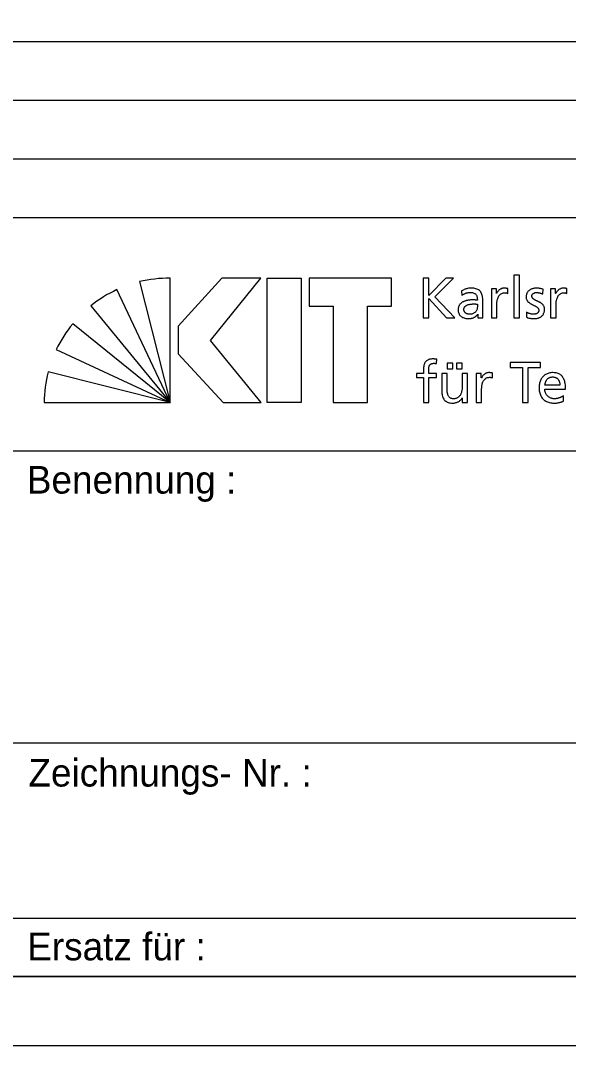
# Model space of a CAD drawing. Extents: x 0 to 8.41, y 0 to 5.94.
# Drawn here: x 7.527 to 7.923, y 0 to 0.742 of the extents above; entities that cross this region are included whole.
import ezdxf

# ---------------------------------------------------------------- set-up
doc = ezdxf.new("R2010")
doc.units = 0
doc.layers.add('90_Plankopf', color=7, linetype='Continuous')

msp = doc.modelspace()

# ---------------------------------------------------------------- linework, layer by layer
at = {"layer": '90_Plankopf'}
for p, q in [((6.5812, 0.7274), (8.36, 0.7274)), ((6.5812, 0.6849), (8.36, 0.6849)), ((6.5812, 0.6424), (8.36, 0.6424)), ((6.5812, 0.5999), (8.36, 0.5999)), ((6.5812, 0.5999), (8.36, 0.5999)), ((7.61275, 0.55333), (7.63481, 0.46586)), ((7.63481, 0.46586), (7.63481, 0.55584)), ((7.8181, 0.55586), (7.8181, 0.52706)), ((7.63481, 0.46586), (7.59633, 0.54752)), ((7.84579, 0.54662), (7.846, 0.54332)), ((7.87926, 0.54484), (7.87926, 0.54831)), ((7.90457, 0.54439), (7.9049, 0.54778)), ((7.92211, 0.54484), (7.92211, 0.54831)), ((7.57744, 0.53585), (7.63481, 0.46586)), ((7.8573, 0.53709), (7.8573, 0.53523)), ((7.86118, 0.53118), (7.86118, 0.53989)), ((7.89297, 0.53118), (7.89277, 0.52772)), ((7.63481, 0.46586), (7.56434, 0.52286)), ((7.8181, 0.52706), (7.82222, 0.52706)), ((7.83506, 0.52706), (7.84108, 0.52706)), ((7.5524, 0.50413), (7.63481, 0.46586)), ((7.82773, 0.49393), (7.8279, 0.49706)), ((7.63481, 0.46586), (7.54658, 0.48788)), ((7.86827, 0.48365), (7.86827, 0.48712)), ((7.91706, 0.47841), (7.90616, 0.47841)), ((7.90616, 0.47552), (7.92119, 0.47552)), ((7.91958, 0.46673), (7.91958, 0.47061)), ((7.54364, 0.46586), (7.63481, 0.46586)), ((7.52001, 0.4307), (8.36, 0.4307)), ((7.52001, 0.2192), (8.36, 0.2192)), ((7.52001, 0.0923), (8.36, 0.0923)), ((8.36, 0.05), (6.5812, 0.05)), ((6.698, 0.05), (8.36, 0.05)), ((6.698, 0.05), (8.36, 0.05))]:
    msp.add_line(p, q, dxfattribs=at)
for points in [[(0, 0), (8.41, 0), (8.41, 5.94), (0, 5.94)], [(0.25, 5.89), (8.36, 5.89), (8.36, 0.05), (0.25, 0.05)], [(7.70066, 0.55586), (7.67236, 0.55586), (7.64073, 0.52099), (7.64073, 0.50092), (7.67338, 0.46586), (7.70085, 0.46586), (7.66422, 0.51063)], [(7.7297, 0.55586), (7.7297, 0.46586), (7.70501, 0.46586), (7.70501, 0.55586)], [(7.73562, 0.55586), (7.73562, 0.5356), (7.75301, 0.5356), (7.75301, 0.46586), (7.77771, 0.46586), (7.77771, 0.5356), (7.7951, 0.5356), (7.7951, 0.55586)]]:
    msp.add_lwpolyline(points, close=True, dxfattribs=at)
for points in [[(7.88381, 0.52706), (7.88768, 0.52706), (7.88768, 0.55801), (7.88381, 0.55801), (7.88381, 0.52706)], [(7.84108, 0.52706), (7.82647, 0.54224), (7.84001, 0.55586), (7.83452, 0.55586), (7.82222, 0.54319), (7.82222, 0.55586), (7.8181, 0.55586)], [(7.87122, 0.54484), (7.87113, 0.54484), (7.87113, 0.5481), (7.8675, 0.5481), (7.8675, 0.52706), (7.87138, 0.52706), (7.87138, 0.53663)], [(7.91407, 0.54484), (7.91398, 0.54484), (7.91398, 0.5481), (7.91035, 0.5481), (7.91035, 0.52706), (7.91423, 0.52706), (7.91423, 0.53663)], [(7.82222, 0.52706), (7.82222, 0.54117), (7.83506, 0.52706)], [(7.85763, 0.52978), (7.85772, 0.52978), (7.85772, 0.52706), (7.86135, 0.52706)], [(7.83554, 0.49426), (7.83554, 0.49013), (7.83942, 0.49013), (7.83942, 0.49426), (7.83554, 0.49426)], [(7.84231, 0.49426), (7.84231, 0.49013), (7.84619, 0.49013), (7.84619, 0.49426), (7.84231, 0.49426)], [(7.8899, 0.46586), (7.89403, 0.46586), (7.89403, 0.49104), (7.90298, 0.49104), (7.90298, 0.49467), (7.88094, 0.49467), (7.88094, 0.49104), (7.8899, 0.49104), (7.8899, 0.46586)], [(7.81824, 0.48885), (7.81824, 0.48691), (7.81329, 0.48691), (7.81329, 0.48378), (7.81824, 0.48378), (7.81824, 0.46586), (7.82212, 0.46586), (7.82212, 0.48378), (7.82769, 0.48378), (7.82769, 0.48691), (7.82212, 0.48691), (7.82212, 0.48918)], [(7.83542, 0.47602), (7.83542, 0.48691), (7.83154, 0.48691), (7.83154, 0.47441)], [(7.85015, 0.46586), (7.85015, 0.48691), (7.84627, 0.48691), (7.84627, 0.47717)], [(7.86022, 0.48365), (7.86014, 0.48365), (7.86014, 0.48691), (7.85651, 0.48691), (7.85651, 0.46586), (7.86039, 0.46586), (7.86039, 0.47544)], [(7.84631, 0.46921), (7.84639, 0.46921), (7.84639, 0.46586), (7.85015, 0.46586)]]:
    msp.add_lwpolyline(points, dxfattribs=at)
for centre, start, end in [((7.63449, 0.46056), 89.80527, 103.18947), ((7.63662, 0.46118), 115.01261, 128.3968), ((7.63816, 0.46263), 140.78977, 154.17397), ((7.63891, 0.46438), 165.72225, 179.10644)]:
    msp.add_arc(centre, 0.09528, start, end, dxfattribs=at)
for points in [[(7.86118, 0.53989), (7.86119, 0.5418), (7.86091, 0.54341), (7.86033, 0.5447), (7.85975, 0.54599), (7.85884, 0.54696), (7.85759, 0.54762), (7.85635, 0.54827), (7.85472, 0.5486), (7.85272, 0.5486), (7.85138, 0.54859), (7.85014, 0.54841), (7.84898, 0.54804), (7.84782, 0.54768), (7.84676, 0.54721), (7.84579, 0.54662)], [(7.846, 0.54332), (7.84653, 0.54376), (7.84713, 0.54414), (7.84779, 0.54446), (7.84846, 0.54478), (7.84916, 0.54503), (7.8499, 0.5452), (7.85063, 0.54538), (7.85137, 0.54546), (7.8521, 0.54546), (7.85339, 0.54546), (7.85441, 0.54526), (7.85518, 0.54485), (7.85594, 0.54444), (7.85649, 0.54383), (7.85682, 0.54302), (7.85715, 0.54219), (7.85731, 0.54118), (7.8573, 0.53997)], [(7.87926, 0.54831), (7.87899, 0.54837), (7.87873, 0.54841), (7.87849, 0.54846), (7.87824, 0.5485), (7.87798, 0.54854), (7.87769, 0.54856), (7.87741, 0.54859), (7.87708, 0.5486), (7.8767, 0.5486), (7.87595, 0.54859), (7.87523, 0.54843), (7.87452, 0.54811), (7.87382, 0.54779), (7.87318, 0.54736), (7.87261, 0.54679), (7.87203, 0.54623), (7.87157, 0.54558), (7.87122, 0.54484)], [(7.87138, 0.53663), (7.87139, 0.5384), (7.87163, 0.53993), (7.8721, 0.54121), (7.87257, 0.54249), (7.87323, 0.54348), (7.87409, 0.54416), (7.87494, 0.54486), (7.87595, 0.54521), (7.87712, 0.54521), (7.87746, 0.54522), (7.8778, 0.54519), (7.87818, 0.54514), (7.87855, 0.54509), (7.87891, 0.54499), (7.87926, 0.54484)], [(7.9049, 0.54778), (7.90414, 0.54801), (7.90337, 0.5482), (7.90259, 0.54836), (7.90181, 0.54851), (7.90097, 0.54859), (7.90007, 0.5486), (7.89903, 0.5486), (7.89805, 0.54847), (7.89716, 0.5482), (7.89625, 0.54794), (7.89547, 0.54753), (7.8948, 0.547), (7.89412, 0.54647), (7.89359, 0.54579), (7.89322, 0.54498), (7.89284, 0.54417), (7.89265, 0.54321), (7.89264, 0.54212), (7.89265, 0.54128), (7.89282, 0.54056), (7.89315, 0.53994), (7.89347, 0.53933), (7.89391, 0.5388), (7.89445, 0.53834), (7.895, 0.5379), (7.89559, 0.5375), (7.89623, 0.53715), (7.89688, 0.5368), (7.89753, 0.53647), (7.89817, 0.53617), (7.89882, 0.53586), (7.89942, 0.53555), (7.89995, 0.53522), (7.9005, 0.5349), (7.90093, 0.53454), (7.90126, 0.53413), (7.90158, 0.53373), (7.90176, 0.53325), (7.90176, 0.53271), (7.90176, 0.53215), (7.90163, 0.53167), (7.90139, 0.53128), (7.90116, 0.5309), (7.90084, 0.53059), (7.90045, 0.53035), (7.90006, 0.53012), (7.89963, 0.52995), (7.89917, 0.52985), (7.89871, 0.52975), (7.89825, 0.5297), (7.8978, 0.5297), (7.89742, 0.5297), (7.89695, 0.52975), (7.89639, 0.52986), (7.89584, 0.52997), (7.89526, 0.53014), (7.89466, 0.53036), (7.89405, 0.53058), (7.8935, 0.53085), (7.89297, 0.53118)], [(7.89277, 0.52772), (7.89366, 0.52726), (7.8946, 0.52694), (7.89558, 0.52678), (7.89656, 0.52662), (7.89755, 0.52655), (7.89854, 0.52656), (7.89949, 0.52656), (7.9004, 0.52669), (7.90127, 0.52695), (7.90215, 0.52722), (7.90293, 0.52762), (7.90363, 0.52816), (7.90431, 0.52869), (7.90487, 0.52938), (7.90527, 0.5302), (7.90568, 0.53103), (7.90588, 0.532), (7.90589, 0.53312), (7.90588, 0.53408), (7.90571, 0.53489), (7.90539, 0.53556), (7.90506, 0.53622), (7.90462, 0.53679), (7.90408, 0.53726), (7.90354, 0.53772), (7.90295, 0.53811), (7.9023, 0.53845), (7.90165, 0.53878), (7.90101, 0.53909), (7.90036, 0.53937), (7.89971, 0.53966), (7.89912, 0.53995), (7.89858, 0.54026), (7.89804, 0.54058), (7.8976, 0.54095), (7.89727, 0.54136), (7.89695, 0.54179), (7.89678, 0.5423), (7.89677, 0.54291), (7.89678, 0.54348), (7.89696, 0.54396), (7.89729, 0.54434), (7.89763, 0.54472), (7.89808, 0.545), (7.89864, 0.54519), (7.8992, 0.54538), (7.89982, 0.54546), (7.90048, 0.54546), (7.90072, 0.54546), (7.90102, 0.54543), (7.90139, 0.54538), (7.90175, 0.54531), (7.90213, 0.54523), (7.90254, 0.54513), (7.90295, 0.54503), (7.90333, 0.54491), (7.90369, 0.54478), (7.90405, 0.54466), (7.90434, 0.54453), (7.90457, 0.54439)], [(7.92211, 0.54831), (7.92184, 0.54837), (7.92158, 0.54841), (7.92134, 0.54846), (7.9211, 0.5485), (7.92083, 0.54854), (7.92054, 0.54856), (7.92026, 0.54859), (7.91993, 0.5486), (7.91955, 0.5486), (7.9188, 0.54859), (7.91808, 0.54843), (7.91737, 0.54811), (7.91667, 0.54779), (7.91603, 0.54736), (7.91546, 0.54679), (7.91488, 0.54623), (7.91442, 0.54558), (7.91407, 0.54484)], [(7.91423, 0.53663), (7.91424, 0.5384), (7.91448, 0.53993), (7.91495, 0.54121), (7.91542, 0.54249), (7.91608, 0.54348), (7.91694, 0.54416), (7.91779, 0.54486), (7.9188, 0.54521), (7.91997, 0.54521), (7.9203, 0.54522), (7.92065, 0.54519), (7.92103, 0.54514), (7.9214, 0.54509), (7.92175, 0.54499), (7.92211, 0.54484)], [(7.8573, 0.53997), (7.8568, 0.54), (7.85633, 0.54002), (7.85589, 0.54003), (7.85546, 0.54004), (7.85502, 0.54005), (7.85459, 0.54006), (7.85415, 0.54006), (7.85368, 0.54006), (7.85318, 0.54006), (7.85237, 0.54006), (7.85151, 0.53999), (7.85063, 0.53984), (7.84973, 0.5397), (7.84886, 0.53947), (7.84801, 0.53914), (7.84715, 0.53881), (7.84638, 0.53838), (7.84569, 0.53785), (7.84499, 0.53731), (7.84444, 0.53665), (7.84403, 0.53588), (7.84362, 0.53509), (7.84341, 0.53418), (7.8434, 0.53312), (7.84341, 0.5316), (7.84374, 0.53035), (7.84439, 0.52939), (7.84504, 0.52842), (7.84594, 0.5277), (7.8471, 0.52724), (7.84825, 0.52679), (7.84959, 0.52656), (7.85111, 0.52656), (7.852, 0.52657), (7.8528, 0.52668), (7.8535, 0.52689), (7.85421, 0.52709), (7.85483, 0.52736), (7.85536, 0.52769), (7.8559, 0.52802), (7.85635, 0.52837), (7.85673, 0.52874), (7.8571, 0.52911), (7.85741, 0.52945), (7.85763, 0.52978)], [(7.8573, 0.53523), (7.8573, 0.53418), (7.85708, 0.53323), (7.85664, 0.5324), (7.8562, 0.53157), (7.85554, 0.53092), (7.85467, 0.53043), (7.8538, 0.52995), (7.85272, 0.5297), (7.85144, 0.5297), (7.851, 0.5297), (7.85054, 0.52978), (7.85008, 0.52992), (7.84963, 0.53007), (7.8492, 0.53028), (7.84882, 0.53057), (7.84843, 0.53087), (7.84812, 0.53123), (7.84789, 0.53165), (7.84765, 0.53207), (7.84753, 0.53257), (7.84752, 0.53312), (7.84754, 0.53386), (7.84772, 0.53448), (7.84808, 0.53497), (7.84844, 0.53546), (7.84891, 0.53586), (7.84949, 0.53615), (7.85007, 0.53645), (7.85069, 0.53667), (7.85135, 0.53682), (7.85201, 0.53696), (7.85265, 0.53706), (7.85326, 0.53711), (7.85387, 0.53715), (7.85439, 0.53717), (7.85483, 0.53717), (7.85524, 0.53717), (7.85565, 0.53715), (7.85607, 0.53713), (7.85648, 0.53711), (7.85689, 0.53709), (7.8573, 0.53709)], [(7.86135, 0.52706), (7.86132, 0.52726), (7.86129, 0.52753), (7.86126, 0.52787), (7.86125, 0.52821), (7.86122, 0.52865), (7.86121, 0.52919), (7.86119, 0.52973), (7.86118, 0.53039), (7.86118, 0.53118)], [(7.8279, 0.49706), (7.82751, 0.49712), (7.8271, 0.49719), (7.82668, 0.49723), (7.82625, 0.49728), (7.82579, 0.49731), (7.8253, 0.49731), (7.82388, 0.4973), (7.8227, 0.4971), (7.82178, 0.49671), (7.82086, 0.49631), (7.82014, 0.49574), (7.81962, 0.495), (7.8191, 0.49426), (7.81875, 0.49337), (7.81854, 0.49233), (7.81833, 0.49129), (7.81824, 0.49014), (7.81824, 0.48885)], [(7.82212, 0.48918), (7.82212, 0.4899), (7.82216, 0.49056), (7.82224, 0.49116), (7.82232, 0.49177), (7.82249, 0.4923), (7.82275, 0.49275), (7.823, 0.4932), (7.82338, 0.49355), (7.82388, 0.49379), (7.82439, 0.49404), (7.82505, 0.49417), (7.82588, 0.49417), (7.82621, 0.49417), (7.82655, 0.49415), (7.82688, 0.49411), (7.82722, 0.49407), (7.8275, 0.49401), (7.82773, 0.49393)], [(7.86827, 0.48712), (7.868, 0.48717), (7.86774, 0.48722), (7.8675, 0.48727), (7.86725, 0.48731), (7.86698, 0.48734), (7.8667, 0.48737), (7.86642, 0.48739), (7.86609, 0.4874), (7.86571, 0.4874), (7.86496, 0.4874), (7.86423, 0.48724), (7.86352, 0.48692), (7.86282, 0.4866), (7.86218, 0.48616), (7.86161, 0.4856), (7.86104, 0.48503), (7.86057, 0.48439), (7.86022, 0.48365)], [(7.86039, 0.47544), (7.86039, 0.47721), (7.86064, 0.47873), (7.8611, 0.48001), (7.86158, 0.48129), (7.86224, 0.48228), (7.8631, 0.48297), (7.86395, 0.48367), (7.86496, 0.48401), (7.86612, 0.48402), (7.86646, 0.48403), (7.86681, 0.484), (7.86718, 0.48395), (7.86756, 0.48389), (7.86791, 0.48379), (7.86827, 0.48365)], [(7.92119, 0.47552), (7.92119, 0.47722), (7.92103, 0.4788), (7.92072, 0.48023), (7.92041, 0.48168), (7.91989, 0.48293), (7.91918, 0.484), (7.91846, 0.48507), (7.91751, 0.48591), (7.91631, 0.4865), (7.91512, 0.48709), (7.91365, 0.4874), (7.9119, 0.4874), (7.91041, 0.4874), (7.90906, 0.48714), (7.90785, 0.48662), (7.90665, 0.4861), (7.90561, 0.48537), (7.90474, 0.48442), (7.90387, 0.48347), (7.90321, 0.48235), (7.90275, 0.48105), (7.90228, 0.47976), (7.90205, 0.47833), (7.90204, 0.47676), (7.90204, 0.47504), (7.90225, 0.47348), (7.90269, 0.47209), (7.90312, 0.47069), (7.90379, 0.4695), (7.90469, 0.4685), (7.90558, 0.46749), (7.90671, 0.46672), (7.90808, 0.46619), (7.90945, 0.46564), (7.91107, 0.46538), (7.91293, 0.46537), (7.91408, 0.46538), (7.91506, 0.46545), (7.91587, 0.4656), (7.91667, 0.46575), (7.91737, 0.46593), (7.91797, 0.46614), (7.91855, 0.46634), (7.91909, 0.46654), (7.91958, 0.46673)], [(7.90616, 0.47841), (7.90623, 0.4791), (7.90639, 0.47978), (7.90664, 0.48047), (7.90688, 0.48116), (7.90722, 0.48179), (7.90768, 0.48236), (7.90812, 0.48294), (7.90869, 0.48339), (7.90937, 0.48374), (7.91006, 0.48408), (7.91087, 0.48426), (7.91182, 0.48427), (7.91266, 0.48426), (7.9134, 0.48411), (7.91404, 0.48381), (7.9147, 0.4835), (7.91524, 0.48309), (7.91569, 0.48255), (7.91614, 0.48201), (7.91648, 0.48139), (7.91671, 0.48069), (7.91694, 0.47998), (7.91706, 0.47922), (7.91706, 0.47841)], [(7.84627, 0.47717), (7.84627, 0.47589), (7.84615, 0.47471), (7.84589, 0.47365), (7.84564, 0.4726), (7.84525, 0.47169), (7.84473, 0.47092), (7.84421, 0.47015), (7.84354, 0.46956), (7.84273, 0.46914), (7.84193, 0.46872), (7.84097, 0.46851), (7.83987, 0.4685), (7.83875, 0.46857), (7.83786, 0.46889), (7.83721, 0.46945), (7.83656, 0.47002), (7.8361, 0.47084), (7.83582, 0.47193), (7.83554, 0.47302), (7.83541, 0.47438), (7.83542, 0.47602)], [(7.91958, 0.47061), (7.91933, 0.47041), (7.91899, 0.47019), (7.91852, 0.46995), (7.91806, 0.46971), (7.91754, 0.46948), (7.91694, 0.46926), (7.91634, 0.46904), (7.91572, 0.46886), (7.91506, 0.46872), (7.9144, 0.46858), (7.91374, 0.46851), (7.91309, 0.4685), (7.91217, 0.46851), (7.9113, 0.46868), (7.91046, 0.46902), (7.90964, 0.46935), (7.90889, 0.46983), (7.90825, 0.47045), (7.90761, 0.47107), (7.9071, 0.47181), (7.90673, 0.47267), (7.90636, 0.47353), (7.90617, 0.47448), (7.90616, 0.47552)], [(7.83154, 0.47441), (7.83154, 0.47251), (7.83181, 0.4709), (7.83237, 0.46955), (7.83293, 0.4682), (7.83379, 0.46717), (7.83496, 0.46645), (7.83612, 0.46574), (7.83761, 0.46538), (7.83942, 0.46537), (7.8404, 0.46538), (7.84135, 0.46553), (7.84225, 0.46583), (7.84315, 0.46614), (7.84396, 0.46658), (7.84466, 0.46715), (7.84537, 0.46772), (7.84592, 0.46841), (7.84631, 0.46921)]]:
    msp.add_open_spline(points, degree=3, dxfattribs=at)

# ---------------------------------------------------------------- texts
for s, p in [('Benennung :', (7.53113, 0.39979)), ('Zeichnungs- Nr. :', (7.53227, 0.18758)), ('Ersatz für :', (7.53139, 0.06169))]:
    msp.add_text(s, height=0.02, dxfattribs=at).set_placement(p)

doc.saveas('drawing.dxf')
